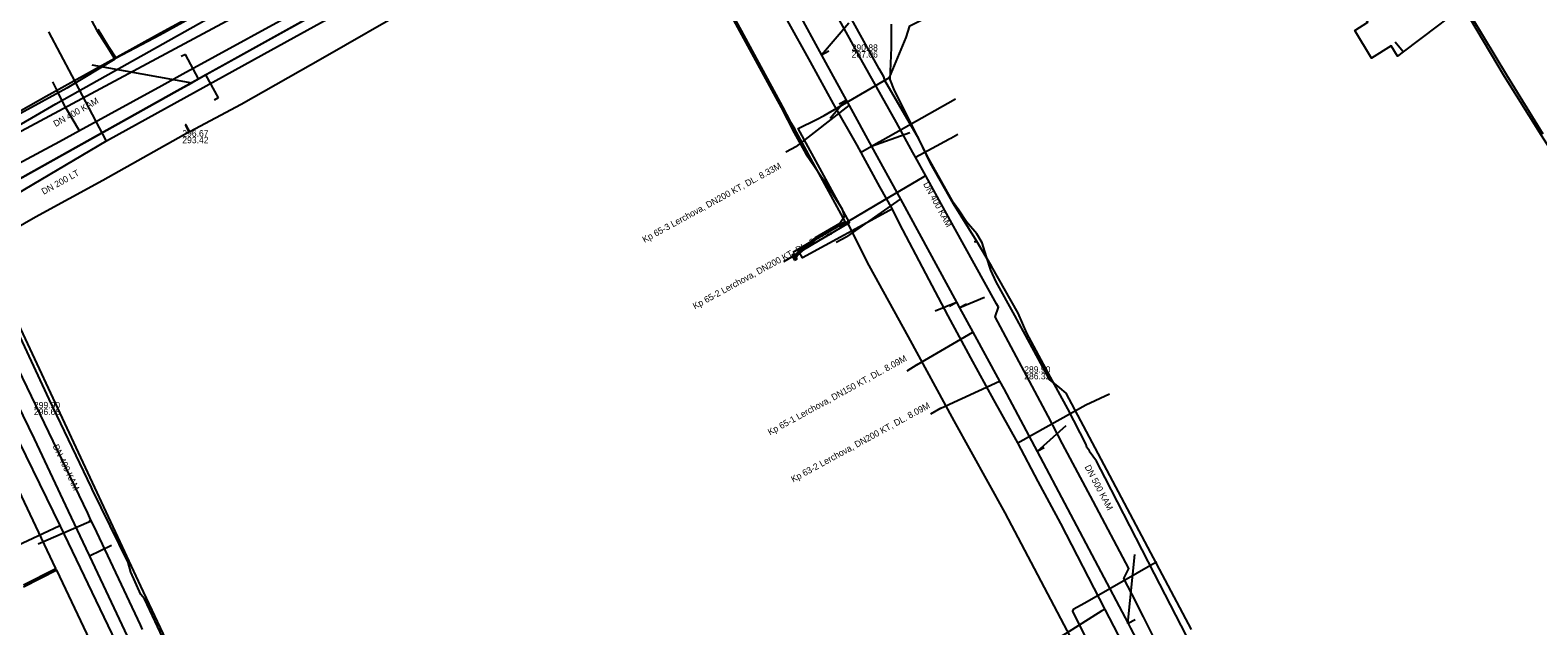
# Model space of a CAD drawing. Extents: x -600391 to -599491, y -1160176 to -1159402.
# Drawn here: x -600145.4 to -599957.1, y -1159881.1 to -1159806.7 of the extents above; entities that cross this region are included whole.
import ezdxf

# ---------------------------------------------------------------- set-up
doc = ezdxf.new("R2010")
doc.units = 0
for name, color, linetype in [('28', 7, 'Continuous'), ('CETIN_linie', 7, 'Continuous'), ('MU_linie', 7, 'Continuous'), ('Vrstva 1', 7, 'Continuous'), ('Vrstva 12', 7, 'Continuous'), ('Vrstva 13', 7, 'Continuous'), ('Vrstva 15', 7, 'Continuous'), ('Vrstva 16', 7, 'Continuous'), ('Vrstva 19', 7, 'Continuous'), ('Vrstva 42', 7, 'Continuous'), ('Vrstva 43', 7, 'Continuous'), ('Vrstva 44', 7, 'Continuous'), ('Vrstva 48', 7, 'Continuous'), ('Vrstva 55', 7, 'Continuous'), ('Vrstva 58', 7, 'Continuous'), ('Vrstva 9', 7, 'Continuous')]:
    doc.layers.add(name, color=color, linetype=linetype)

# ---------------------------------------------------------------- blocks, each defined once
blk = doc.blocks.new('NN620')
at = {"layer": '28'}
for points in [[(0.75, 0), (-0.75, 0)], [(-0.75, 0), (-0.75, -0.75)], [(0.75, -0.75), (0.75, 0)], [(-0.75, -0.75), (0.75, -0.75)], [(0.37, -0.18), (-0.38, -0.18)], [(-0.38, -0.18), (-0.38, -0.56)], [(-0.38, -0.56), (0.37, -0.56)], [(0.32, -0.23), (-0.33, -0.23)], [(-0.33, -0.23), (-0.33, -0.51)], [(-0.33, -0.51), (0.32, -0.51)], [(0.27, -0.27), (-0.28, -0.27)], [(-0.28, -0.27), (-0.28, -0.46)], [(-0.28, -0.46), (0.27, -0.46)], [(0.23, -0.32), (-0.23, -0.32)], [(-0.23, -0.32), (-0.23, -0.42)], [(-0.23, -0.42), (0.23, -0.42)], [(-0.19, -0.37), (0.19, -0.37)], [(0.23, -0.42), (0.23, -0.32)], [(0.27, -0.46), (0.27, -0.27)], [(0.32, -0.51), (0.32, -0.23)], [(0.37, -0.56), (0.37, -0.18)]]:
    blk.add_lwpolyline(points, dxfattribs=at)

msp = doc.modelspace()

# ---------------------------------------------------------------- linework, layer by layer
at = {"layer": 'CETIN_linie'}
for points in [[(-600155.82, -1159824.25), (-600096.42, -1159792.4), (-600032.25, -1159754.89)], [(-600155.82, -1159824.25), (-600131.59, -1159876.14), (-600105.43, -1159931.66), (-600079.78, -1159985.02), (-600054.68, -1160038.07), (-600031.21, -1160088.32), (-600065.96, -1160109.81), (-600092.69, -1160126.24), (-600115.43, -1160139.89), (-600155.2, -1160162.97), (-600165.23, -1160150.94)]]:
    msp.add_lwpolyline(points, dxfattribs=at)
at = {"layer": 'MU_linie'}
msp.add_lwpolyline([(-600004.67, -1159873.12), (-600005.18, -1159873.36), (-600007.15, -1159874.51), (-600013.69, -1159878.26), (-600015.14, -1159879.03), (-600015.22, -1159879.27), (-600012.72, -1159884.3), (-600009.27, -1159891.11), (-600009.32, -1159891.33), (-600009.58, -1159891.5), (-600011.58, -1159892.29), (-600014.72, -1159894.28), (-600016.52, -1159895.03)], dxfattribs=at)
at = {"layer": 'Vrstva 1'}
for points in [[(-600094.93, -1159796.4), (-600127.04, -1159814.25)], [(-600043.13, -1159805.81), (-600046.54, -1159809.78)], [(-600125.98, -1159809.69), (-600126.54, -1159809.96)], [(-600124.34, -1159812.75), (-600125.98, -1159809.69)], [(-600137.67, -1159810.99), (-600125.21, -1159813.24)], [(-600123.47, -1159812.26), (-600121.91, -1159815.13)], [(-600127.04, -1159814.25), (-600157.56, -1159831.33)], [(-600121.91, -1159815.13), (-600122.39, -1159815.43)], [(-600043.5, -1159815.4), (-600045.49, -1159817.69)], [(-600035.54, -1159819.48), (-600040.32, -1159821.19)], [(-600026.18, -1159840.07), (-600029.3, -1159841.34)], [(-600029.7, -1159840.67), (-600032.35, -1159841.79)], [(-600016.06, -1159856.1), (-600019.64, -1159859.32)], [(-600135.24, -1159871.06), (-600137.97, -1159872.37)], [(-600008.28, -1159880.78), (-600007.41, -1159872.16)]]:
    msp.add_lwpolyline(points, dxfattribs=at)
at = {"layer": 'Vrstva 13'}
for points in [[(-600158.57, -1159833.83), (-600154.25, -1159831.35), (-600135.85, -1159820.51), (-600116.14, -1159809.61), (-600100.05, -1159800.72), (-600081.77, -1159790.54), (-600067.01, -1159782.23), (-600066.24, -1159781.79)], [(-600061.44, -1159786.09), (-600060.81, -1159787.29), (-600057.69, -1159792.41), (-600054.89, -1159797.57), (-600053.57, -1159800.14), (-600050.85, -1159805.45), (-600047.98, -1159810.63), (-600045.09, -1159815.85), (-600042.15, -1159821.02), (-600039.31, -1159826.25), (-600037.74, -1159829.01), (-600036.85, -1159830.81), (-600033.58, -1159837.07), (-600030.77, -1159842.35), (-600027.94, -1159847.61), (-600025.07, -1159852.86), (-600022.08, -1159858.24), (-600019.52, -1159863.07), (-600016.7, -1159868.3), (-600011.18, -1159879.03), (-600008.99, -1159883.21)], [(-600135.85, -1159820.51), (-600135.89, -1159820.45), (-600140.14, -1159812.39), (-600143.05, -1159806.87)], [(-600041.66, -1159821.93), (-600041.48, -1159821.83), (-600029.82, -1159815.23)], [(-600037.74, -1159829.01), (-600038.06, -1159829.19), (-600048.92, -1159835.11), (-600049.31, -1159834.44), (-600051.32, -1159835.59)], [(-600080.79, -1159998.87), (-600081.22, -1159997.9), (-600084.08, -1159991.85), (-600086.71, -1159986.33), (-600092.25, -1159974.69), (-600092.88, -1159973.3), (-600095.81, -1159966.83), (-600099.22, -1159959.42), (-600104.56, -1159947.82), (-600110.84, -1159933.71), (-600113.13, -1159928.57), (-600117.44, -1159919.3), (-600122.36, -1159908.74), (-600128.42, -1159895.95), (-600135.15, -1159882.07), (-600141.58, -1159868.63), (-600148.44, -1159854.56), (-600156.4, -1159838.21), (-600158.07, -1159834.85)], [(-600022.08, -1159858.24), (-600021.76, -1159858.06), (-600013.53, -1159853.47), (-600010.58, -1159852.08)], [(-600141.58, -1159868.63), (-600141.74, -1159868.63), (-600147.64, -1159871.38)], [(-600011.18, -1159879.03), (-600011.56, -1159879.23), (-600016.08, -1159882.07), (-600023.64, -1159886.58)]]:
    msp.add_lwpolyline(points, dxfattribs=at)
at = {"layer": 'Vrstva 16'}
for points in [[(-600004.45, -1159883.69), (-600006.35, -1159879.97), (-600007.81, -1159877.08), (-600008.78, -1159875.16), (-600008.16, -1159873.92), (-600012.63, -1159865.51), (-600016.44, -1159858.35), (-600018.26, -1159854.91), (-600024.88, -1159842.47), (-600024.46, -1159841.28), (-600024.69, -1159840.86), (-600026.18, -1159838.17), (-600031.15, -1159829.18), (-600033.54, -1159824.86), (-600034.81, -1159822.55), (-600035.14, -1159821.97), (-600037.21, -1159818.22), (-600041.59, -1159810.32), (-600043.06, -1159807.66), (-600048.32, -1159798.16), (-600054.16, -1159787.6), (-600054.73, -1159787.42), (-600055.73, -1159785.4)], [(-600030.6, -1159820.25), (-600030.4, -1159820.14), (-600029.55, -1159819.67)], [(-600034.81, -1159822.55), (-600030.66, -1159820.28), (-600030.6, -1159820.25)], [(-600033.54, -1159824.86), (-600033.77, -1159825), (-600038.93, -1159828.04), (-600044.37, -1159831.25)]]:
    msp.add_lwpolyline(points, dxfattribs=at)
at = {"layer": 'Vrstva 19'}
for points in [[(-600109.7, -1159803.08), (-600126.31, -1159812.18), (-600128.94, -1159813.62), (-600139.2, -1159819.24), (-600141.71, -1159820.61), (-600150.98, -1159825.58)], [(-600139.2, -1159819.24), (-600140.93, -1159816.39), (-600141.7, -1159814.82), (-600142.04, -1159814.13), (-600142.53, -1159813.13)], [(-600154.52, -1159833.2), (-600138.21, -1159867), (-600137.84, -1159867.9), (-600137.42, -1159868.68), (-600131.64, -1159880.94), (-600131.38, -1159881.54)], [(-600137.84, -1159867.9), (-600137.98, -1159867.96), (-600137.94, -1159868.09), (-600138.07, -1159868.14), (-600144.36, -1159870.9)]]:
    msp.add_lwpolyline(points, dxfattribs=at)
at = {"layer": 'Vrstva 42'}
for points in [[(-600077.44, -1159770.44), (-600077.24, -1159770.33), (-600076.67, -1159770.64), (-600074.02, -1159775.39), (-600072.9, -1159776.6), (-600066.33, -1159789.64), (-600061.3, -1159798.52), (-600056.78, -1159806.8), (-600052.29, -1159815.04), (-600051.59, -1159816.33), (-600049.98, -1159819.49), (-600048.51, -1159822.11), (-600046.26, -1159825.41), (-600044.01, -1159828.94), (-600043.69, -1159829.95), (-600044.27, -1159830.84), (-600047.33, -1159832.6), (-600049.42, -1159834.33), (-600049.85, -1159834.85)], [(-600047.18, -1159817.83), (-600046.22, -1159817.31), (-600038.05, -1159812.57), (-600035.99, -1159807.6), (-600035.52, -1159806.11), (-600031.64, -1159804.19), (-600016.71, -1159794.79), (-600012.52, -1159792.52), (-600006.93, -1159789.35), (-600002, -1159787.36), (-600001.14, -1159787.11), (-599999.2, -1159785.35), (-599998.2, -1159784.84), (-599996.22, -1159787.14), (-599995.69, -1159787.9), (-599994.82, -1159789.39), (-599994.86, -1159789.62)], [(-599956.45, -1159819.68), (-599960.97, -1159812.3), (-599965.34, -1159805.05), (-599969.65, -1159797.56), (-599973.03, -1159791.78), (-599973.33, -1159791.42), (-599974.7, -1159789.95), (-599975.85, -1159789.4), (-599976.54, -1159789.4), (-599977.48, -1159789.89), (-599978.79, -1159790.3), (-599979.99, -1159790.27), (-599983.43, -1159789.95), (-599989.43, -1159789.35), (-599992.92, -1159789.66), (-599994.51, -1159790.23)], [(-599945.28, -1159836.53), (-599945.63, -1159836.09), (-599945.66, -1159835.92), (-599946.62, -1159834.69), (-599950.74, -1159829.06), (-599956.66, -1159819.81), (-599961.25, -1159812.44), (-599965.59, -1159805.18), (-599970.2, -1159797.19), (-599973.48, -1159791.54), (-599974.84, -1159790.19), (-599975.94, -1159789.67), (-599976.48, -1159789.69), (-599977.44, -1159790.14), (-599978.77, -1159790.54), (-599980.03, -1159790.54), (-599983.54, -1159790.26), (-599989.48, -1159789.72), (-599992.75, -1159789.99), (-599994.4, -1159790.47)], [(-600061.12, -1159798.42), (-600056.6, -1159806.7), (-600051.41, -1159816.23), (-600050.43, -1159818.15), (-600049.94, -1159818.96)], [(-600120.21, -1159802.28), (-600129.17, -1159807.28), (-600134.62, -1159810.18), (-600135.58, -1159808.71), (-600136.88, -1159806.59)], [(-600137.73, -1159805.46), (-600137.06, -1159806.69), (-600135.74, -1159808.81), (-600134.8, -1159810.28), (-600140.79, -1159813.9), (-600152.87, -1159820.51)], [(-600050.09, -1159834.39), (-600043.6, -1159830.55), (-600049.94, -1159818.96)], [(-600049.9, -1159834.75), (-600043.07, -1159830.69), (-600049.45, -1159818.96), (-600047.18, -1159817.83)], [(-600015.06, -1159883.26), (-600023.6, -1159866.96), (-600029.98, -1159855.47), (-600035.68, -1159844.98), (-600040.62, -1159836.05), (-600043.18, -1159830.96), (-600044.13, -1159830.98), (-600047.21, -1159832.76), (-600049.28, -1159834.47), (-600049.69, -1159834.97)], [(-600146.23, -1159875.96), (-600142.18, -1159873.91), (-600155.38, -1159846.06)], [(-600132.65, -1159893.98), (-600142.06, -1159874.13), (-600146.23, -1159876.24)]]:
    msp.add_lwpolyline(points, dxfattribs=at)
at = {"layer": 'Vrstva 44'}
msp.add_lwpolyline([(-600150.7, -1159819.03), (-600143.39, -1159814.93), (-600129.11, -1159807.01), (-600119.84, -1159801.93), (-600111.72, -1159797.21), (-600105.56, -1159793.86), (-600100.79, -1159791.19), (-600093.08, -1159787.03), (-600087.16, -1159783.82), (-600080.81, -1159780.39), (-600071.38, -1159775.31), (-600065.86, -1159772.47), (-600064.48, -1159771.6), (-600064.26, -1159771.26), (-600064.31, -1159771.09), (-600064.51, -1159770.54), (-600064.92, -1159769.68)], dxfattribs=at)
at = {"layer": 'Vrstva 48'}
for points in [[(-599980.26, -1159802.65), (-599973.43, -1159798.13), (-599972.11, -1159800.02), (-599968.45, -1159805.26), (-599969.66, -1159806.18), (-599973.93, -1159809.39), (-599974.62, -1159809.91), (-599975.43, -1159808.61), (-599977.86, -1159810.15), (-599979.97, -1159806.71), (-599978.33, -1159805.68), (-599980.26, -1159802.65)], [(-599973.93, -1159809.39), (-599974.9, -1159808.15)]]:
    msp.add_lwpolyline(points, dxfattribs=at)
at = {"layer": 'Vrstva 55'}
for points in [[(-600070.35, -1159787.62), (-600070.42, -1159787.69), (-600071.48, -1159789.07), (-600078.39, -1159793.19), (-600080.55, -1159794.15), (-600087.34, -1159797.87), (-600097.69, -1159803.79), (-600098.12, -1159803.09), (-600098.24, -1159802.93), (-600098.22, -1159803.15), (-600097.79, -1159803.85), (-600108.81, -1159810.18), (-600119.01, -1159815.94), (-600125.46, -1159819.36), (-600125.88, -1159818.53), (-600125.96, -1159818.45), (-600126, -1159818.57), (-600125.56, -1159819.42), (-600136.32, -1159825.44), (-600144.71, -1159830.04), (-600148.85, -1159832.39), (-600148.34, -1159833.3)], [(-600013.07, -1159859.24), (-600013.41, -1159858.79), (-600013.49, -1159858.41), (-600015.81, -1159853.96), (-600017.96, -1159850.03), (-600020.93, -1159844.53), (-600021.98, -1159842.01), (-600025.31, -1159836.14), (-600027.21, -1159832.98), (-600027.42, -1159833.11), (-600027.21, -1159832.98), (-600030.06, -1159828.36), (-600032.94, -1159823.27), (-600034.42, -1159820.24), (-600038.66, -1159812.97), (-600038.77, -1159812.51), (-600039.36, -1159811.51), (-600046.39, -1159798.76), (-600053.12, -1159786.91)], [(-600125.87, -1159888.86), (-600131.09, -1159877.7), (-600131.54, -1159877.19), (-600132.81, -1159874.38), (-600133.13, -1159873.19), (-600137.62, -1159864.03), (-600137.71, -1159863.8), (-600143.01, -1159852.76), (-600149.96, -1159837.89)], [(-600000.3, -1159883.62), (-600004.96, -1159874.59), (-600011.15, -1159862.58), (-600012.22, -1159860.51), (-600013.12, -1159859.25)]]:
    msp.add_lwpolyline(points, dxfattribs=at)
at = {"layer": 'Vrstva 58'}
for points in [[(-600163.55, -1159828.33), (-600142.16, -1159815.89), (-600072.6, -1159776.79), (-600060.95, -1159769.42), (-600017.02, -1159744.89), (-600014.64, -1159741.49), (-599987.16, -1159725.02), (-599986.62, -1159715.61), (-599975.61, -1159709.35), (-599996.37, -1159670.2), (-599997.79, -1159663.38)], [(-600000.34, -1159881.54), (-600016.01, -1159852.03), (-600016.79, -1159851.33), (-600018.09, -1159850.32), (-600022.41, -1159842.31), (-600024.75, -1159838.09), (-600025.42, -1159836.64), (-600025.95, -1159834.98), (-600026.5, -1159833.24), (-600027.17, -1159832.12), (-600028.43, -1159830.6), (-600029.42, -1159829.17), (-600030.06, -1159828.22), (-600033.14, -1159822.76), (-600037.42, -1159814.2), (-600037.98, -1159812.83), (-600037.8, -1159808.83), (-600037.8, -1159805.93)]]:
    msp.add_lwpolyline(points, dxfattribs=at)
at = {"layer": 'Vrstva 9'}
for p, q in [((-600045.66, -1159809.31), (-600046.54, -1159809.78)), ((-600044.36, -1159815.88), (-600043.48, -1159815.4)), ((-600049.66, -1159821.21), (-600043.11, -1159816.09)), ((-600049.66, -1159821.21), (-600051, -1159821.89)), ((-600039.44, -1159820.71), (-600040.32, -1159821.19)), ((-600043.4, -1159832.48), (-600036.71, -1159827.8)), ((-600043.4, -1159832.48), (-600044.73, -1159833.18)), ((-600030.57, -1159841.14), (-600029.69, -1159840.66)), ((-600028.43, -1159840.88), (-600029.31, -1159841.36)), ((-600034.63, -1159848.49), (-600027.64, -1159844.41)), ((-600034.63, -1159848.49), (-600035.92, -1159849.25)), ((-600031.67, -1159853.88), (-600024.32, -1159850.5)), ((-600031.67, -1159853.88), (-600032.95, -1159854.66)), ((-600018.75, -1159858.86), (-600019.63, -1159859.32)), ((-600007.39, -1159880.34), (-600008.27, -1159880.8))]:
    msp.add_line(p, q, dxfattribs=at)
for points in [[(-600056.83, -1159790.83), (-600056.4, -1159791.62), (-600055.96, -1159792.43), (-600055.66, -1159792.99), (-600046.54, -1159809.78), (-600046.04, -1159810.71)], [(-600127.04, -1159814.25), (-600125.21, -1159813.24), (-600125.14, -1159813.19), (-600124.34, -1159812.75), (-600124.27, -1159812.71), (-600123.47, -1159812.26), (-600123.38, -1159812.21), (-600097.77, -1159797.98), (-600097.73, -1159797.96), (-600096.9, -1159797.49), (-600096.86, -1159797.47), (-600096.02, -1159797.01), (-600095.93, -1159796.96), (-600094.93, -1159796.4)], [(-600046.04, -1159810.71), (-600043.48, -1159815.4), (-600043.11, -1159816.09), (-600040.32, -1159821.19), (-600036.71, -1159827.8), (-600029.69, -1159840.66), (-600029.31, -1159841.36), (-600027.64, -1159844.41), (-600024.32, -1159850.5), (-600023.79, -1159851.47)], [(-600157.53, -1159831.32), (-600149.7, -1159826.94), (-600149.44, -1159826.8), (-600149.09, -1159826.61), (-600148.83, -1159826.46), (-600127.04, -1159814.25)], [(-600144.85, -1159857.74), (-600149.07, -1159848.99), (-600149.12, -1159848.89), (-600153.68, -1159839.44), (-600153.91, -1159838.96), (-600157.53, -1159831.32)], [(-600023.79, -1159851.47), (-600019.63, -1159859.32), (-600008.27, -1159880.8), (-600007.97, -1159881.37), (-600001.14, -1159894.29)], [(-600131.84, -1159885.31), (-600137.94, -1159872.38), (-600138.02, -1159872.21), (-600140.59, -1159866.76), (-600140.6, -1159866.75), (-600144.85, -1159857.74)]]:
    msp.add_lwpolyline(points, dxfattribs=at)

# ---------------------------------------------------------------- block references
at = {"layer": 'Vrstva 43', "xscale": 0.5, "yscale": 0.5, "rotation": -61.000000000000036}
msp.add_blockref('NN620', (-600049.77, -1159834.91), dxfattribs=at)

# ---------------------------------------------------------------- texts
at = {"layer": 'Vrstva 12'}
for s, p in [('290.88', (-600042.79, -1159809.25)), ('287.06', (-600042.79, -1159810.09)), ('296.67', (-600126.38, -1159819.96)), ('293.42', (-600126.38, -1159820.79)), ('289.90', (-600021.24, -1159849.46)), ('286.32', (-600021.24, -1159850.29)), ('299.90', (-600144.91, -1159853.91)), ('296.68', (-600144.91, -1159854.74))]:
    msp.add_text(s, height=0.8, dxfattribs=at).set_placement(p)
for s, rotation, p in [('DN 400 KAM', 29.2208, (-600142.2, -1159818.78)), ('Kp 65-3 Lerchova, DN200 KT, DL. 8.33M', 28.6671, (-600068.66, -1159833.25)), ('DN 400 KAM', 298.6309, (-600033.89, -1159825.89)), ('Kp 65-2 Lerchova, DN200 KT, DL. 8.17M', 28.6671, (-600062.36, -1159841.56)), ('Kp 65-1 Lerchova, DN150 KT, DL. 8.09M', 28.6671, (-600052.99, -1159857.3)), ('Kp 63-2 Lerchova, DN200 KT, DL. 8.09M', 28.6671, (-600050.09, -1159863.19)), ('DN 400 KAM', 295.3024, (-600142.59, -1159858.63)), ('DN 500 KAM', 297.8775, (-600013.72, -1159861.23))]:
    msp.add_text(s, height=0.8, rotation=rotation, dxfattribs=at).set_placement(p)
at = {"layer": 'Vrstva 15'}
msp.add_text('DN 200 LT', height=0.8, rotation=28.9344, dxfattribs=at).set_placement((-600143.69, -1159827.25))

doc.saveas('drawing.dxf')
